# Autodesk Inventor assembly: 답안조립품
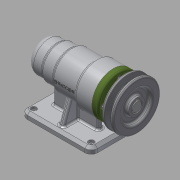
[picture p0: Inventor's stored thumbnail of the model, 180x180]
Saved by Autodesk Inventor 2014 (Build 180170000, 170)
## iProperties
Created: 2016-06
Part Number: 답안조립품
Document SubType Name: Assembly
Designer: SCD-A13
Author: SCD-A13
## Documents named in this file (12)
- C:\Users\SCD-A13\Desktop\460607V1002\답안조립품.iam
- C:\Users\SCD-A13\Desktop\460607V1002\본체.ipt
- C:\Users\SCD-A13\Desktop\460607V1002\V벨트풀리.ipt
- C:\Users\SCD-A13\Desktop\460607V1002\멈춤나사 M3x8.ipt
- C:\Users\SCD-A13\Desktop\460607V1002\베어링 6004.ipt
- C:\Users\SCD-A13\Desktop\460607V1002\베어링 51202.ipt
- C:\Users\SCD-A13\Desktop\460607V1002\볼트 M4 x 12.ipt
- C:\Users\SCD-A13\Desktop\460607V1002\어댑터슬리브.ipt
- C:\Users\SCD-A13\Desktop\460607V1002\오일 실.ipt
- C:\Users\SCD-A13\Desktop\460607V1002\축.ipt
- C:\Users\SCD-A13\Desktop\460607V1002\커버.ipt
- C:\Users\SCD-A13\Desktop\460607V1002\키 5 x 5 x 16.ipt
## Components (6 placed, 2 different names)
1. V벨트풀리:1
2. ISO 4762 M4 x 12:1
3. ISO 4762 M4 x 12:2
4. ISO 4762 M4 x 12:3
5. ISO 4762 M4 x 12:4
6. ISO 4762 M4 x 12:5
